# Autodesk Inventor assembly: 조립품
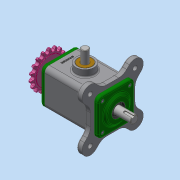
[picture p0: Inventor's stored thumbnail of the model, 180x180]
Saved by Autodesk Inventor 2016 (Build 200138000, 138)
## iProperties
Created: 2019-11
Part Number: 조립품
Material: 일반
Document SubType Name: Assembly
Designer: user
Author: user
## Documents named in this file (11)
- C:\Users\user\Desktop\491109V1006\조립품.iam
- C:\Users\user\Desktop\491109V1006\베어링 6203.ipt
- C:\Users\user\Desktop\491109V1006\본체.ipt
- C:\Users\user\Desktop\491109V1006\볼트 M4.ipt
- C:\Users\user\Desktop\491109V1006\부시.ipt
- C:\Users\user\Desktop\491109V1006\스프로킷.ipt
- C:\Users\user\Desktop\491109V1006\슬라이더.ipt
- C:\Users\user\Desktop\491109V1006\오일 실.ipt
- C:\Users\user\Desktop\491109V1006\커버.ipt
- C:\Users\user\Desktop\491109V1006\키 4 x 4 x 14.ipt
- C:\Users\user\Desktop\491109V1006\편심축.ipt
